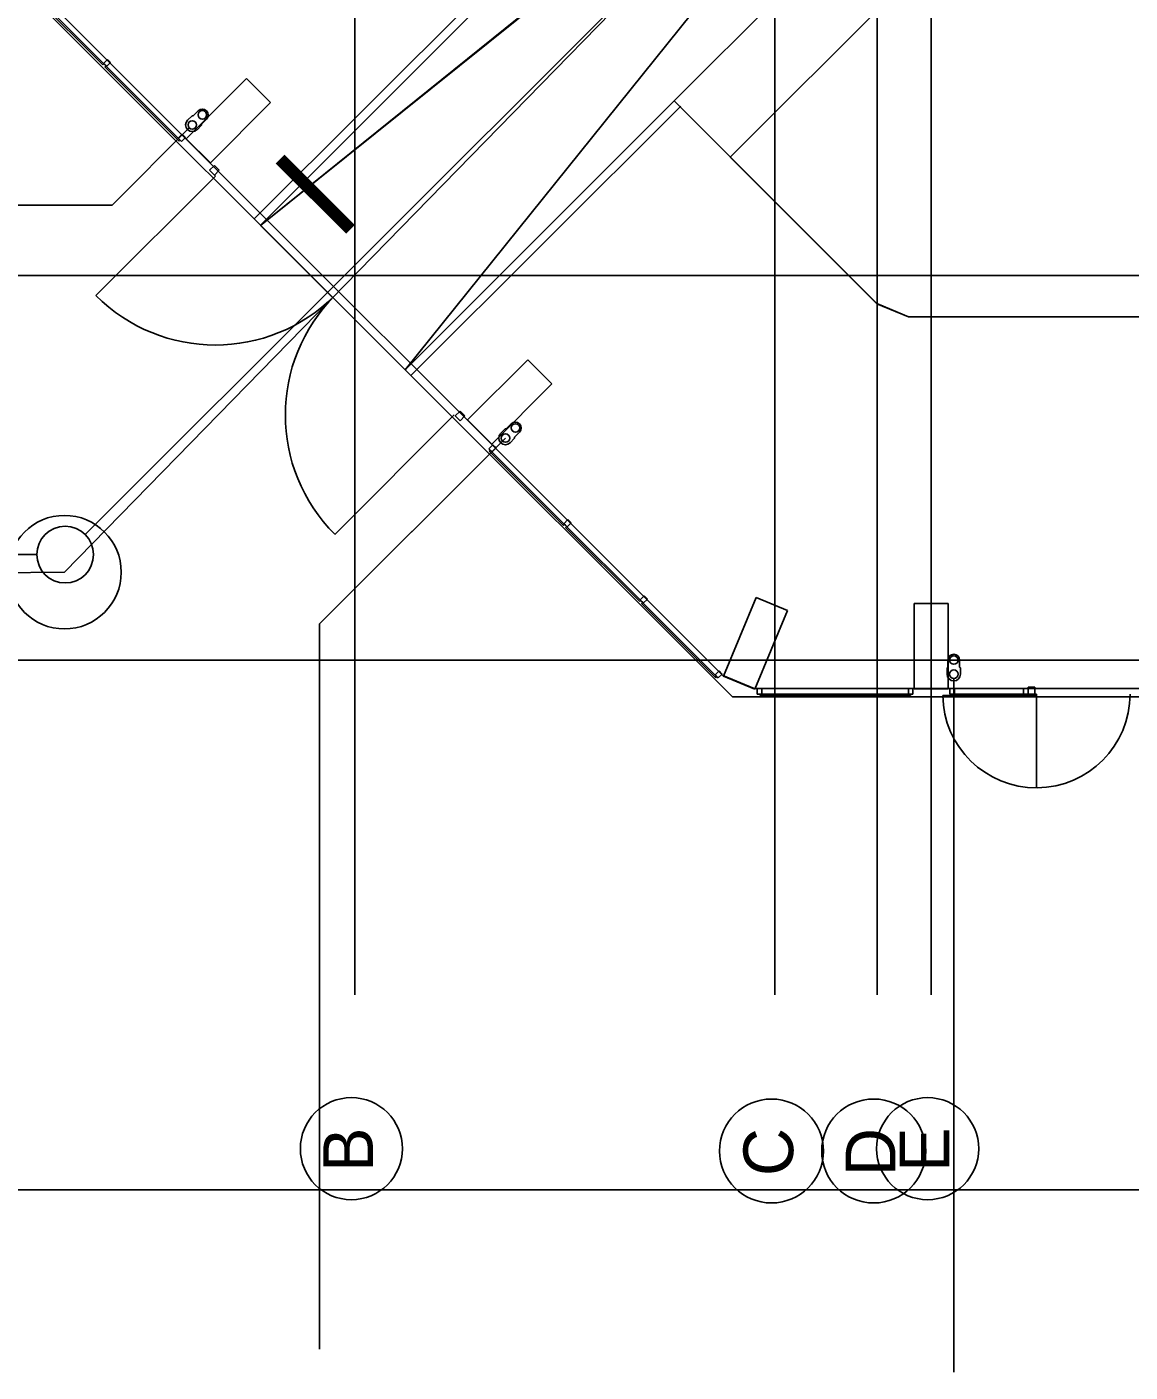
# Model space of a CAD drawing. Extents: x -264205 to -263659, y -1242401 to -1242060.
# Drawn here: x -263907.39 to -263887.96, y -1242253.35 to -1242229.65 of the extents above; entities that cross this region are included whole.
import ezdxf

# ---------------------------------------------------------------- set-up
doc = ezdxf.new("R2010")
doc.units = 0
for name, color, linetype in [('KFA_SO_40-2-II_DAZDOVA_KANALIZACIA', 7, 'Continuous'), ('OBRUBNIKY_KOMUNIKACIE_PROJEKT', 7, 'Continuous'), ('OSI_STAVBY_KFA', 7, 'Continuous'), ('SITUACIA_DSP_2D', 7, 'Continuous')]:
    doc.layers.add(name, color=color, linetype=linetype)

msp = doc.modelspace()

# ---------------------------------------------------------------- linework, layer by layer
at = {"layer": 'KFA_SO_40-2-II_DAZDOVA_KANALIZACIA'}
msp.add_line((-263926.723, -1242239.4), (-263906.731, -1242239.259), dxfattribs=at)
msp.add_lwpolyline([(-263814.907, -1242107.856), (-263815.198, -1242164.443), (-263815.189, -1242220.791), (-263852.152, -1242220.736), (-263888.701, -1242220.786), (-263906.731, -1242239.259)], dxfattribs=at)
msp.add_circle((-263906.731, -1242239.259), 1, dxfattribs=at)
at = {"layer": 'OBRUBNIKY_KOMUNIKACIE_PROJEKT'}
for p, q in [((-263890.254, -1242222.659), (-263903.277, -1242233.148)), ((-263900.731, -1242235.694), (-263890.254, -1242222.659)), ((-263895.995, -1242230.956), (-263890.391, -1242225.352)), ((-263894.968, -1242241.457), (-263909.043, -1242227.382)), ((-263898.65, -1242228.301), (-263903.39, -1242233.035)), ((-263898.544, -1242228.407), (-263903.281, -1242233.144)), ((-263900.731, -1242235.694), (-263895.982, -1242230.943)), ((-263892.424, -1242234.526), (-263895.994, -1242230.956)), ((-263900.629, -1242235.796), (-263895.875, -1242231.049)), ((-263903.39, -1242233.035), (-263900.629, -1242235.796)), ((-263903.281, -1242233.144), (-263900.731, -1242235.694)), ((-263903.277, -1242233.148), (-263900.731, -1242235.694)), ((-263891.868, -1242234.757), (-263892.424, -1242234.526)), ((-263822.79, -1242234.757), (-263891.868, -1242234.757)), ((-263822.79, -1242241.457), (-263894.968, -1242241.457))]:
    msp.add_line(p, q, dxfattribs=at)
at = {"layer": 'OSI_STAVBY_KFA'}
for p, q in [((-263901.618, -1242083.237), (-263901.618, -1242246.707)), ((-263894.218, -1242083.237), (-263894.218, -1242246.707)), ((-263892.418, -1242083.237), (-263892.418, -1242246.707)), ((-263891.468, -1242083.237), (-263891.468, -1242246.707)), ((-263792.653, -1242234.032), (-263911.523, -1242234.032)), ((-263792.653, -1242240.807), (-263911.523, -1242240.807))]:
    msp.add_line(p, q, dxfattribs=at)
for centre, radius in [((-263901.678, -1242249.416), 0.899), ((-263894.278, -1242249.457), 0.916), ((-263892.478, -1242249.457), 0.916), ((-263891.528, -1242249.416), 0.899)]:
    msp.add_circle(centre, radius, dxfattribs=at)
at = {"layer": 'SITUACIA_DSP_2D'}
for p, q in [((-263889.023, -1242221.253), (-263906.365, -1242238.596)), ((-263890.333, -1242222.748), (-263903.277, -1242233.148)), ((-263900.731, -1242235.694), (-263890.333, -1242222.748)), ((-263895.995, -1242230.956), (-263890.391, -1242225.352)), ((-263894.968, -1242241.457), (-263909.043, -1242227.382)), ((-263908.663, -1242227.55), (-263895.135, -1242241.078)), ((-263895.005, -1242231.945), (-263891.01, -1242227.95)), ((-263891.01, -1242227.95), (-263895.005, -1242231.945)), ((-263898.65, -1242228.301), (-263903.39, -1242233.035)), ((-263898.544, -1242228.407), (-263903.281, -1242233.144)), ((-263906.055, -1242230.32), (-263907.363, -1242229.012)), ((-263907.345, -1242228.994), (-263906.037, -1242230.303)), ((-263906.037, -1242230.303), (-263906.055, -1242230.32)), ((-263906.046, -1242230.294), (-263905.975, -1242230.223)), ((-263906.017, -1242230.322), (-263906.046, -1242230.294)), ((-263905.989, -1242230.351), (-263906.017, -1242230.322)), ((-263905.918, -1242230.28), (-263905.989, -1242230.351)), ((-263905.975, -1242230.223), (-263905.918, -1242230.28)), ((-263906.019, -1242230.356), (-263906.001, -1242230.338)), ((-263904.711, -1242231.664), (-263906.019, -1242230.356)), ((-263906.001, -1242230.338), (-263904.693, -1242231.647)), ((-263903.526, -1242230.561), (-263904.586, -1242231.622)), ((-263903.101, -1242230.985), (-263903.526, -1242230.561)), ((-263904.162, -1242232.046), (-263903.101, -1242230.985)), ((-263900.731, -1242235.694), (-263895.982, -1242230.943)), ((-263892.424, -1242234.526), (-263895.994, -1242230.956)), ((-263904.484, -1242231.218), (-263904.563, -1242231.296)), ((-263904.465, -1242231.218), (-263904.484, -1242231.218)), ((-263904.376, -1242231.13), (-263904.465, -1242231.218)), ((-263904.231, -1242231.275), (-263904.319, -1242231.364)), ((-263900.629, -1242235.796), (-263895.875, -1242231.049)), ((-263904.533, -1242231.432), (-263905.894, -1242232.793)), ((-263904.397, -1242231.462), (-263904.319, -1242231.383)), ((-263904.319, -1242231.383), (-263904.397, -1242231.462)), ((-263904.319, -1242231.364), (-263904.319, -1242231.383)), ((-263904.726, -1242231.613), (-263904.656, -1242231.543)), ((-263904.698, -1242231.642), (-263904.726, -1242231.613)), ((-263904.693, -1242231.647), (-263904.711, -1242231.664)), ((-263904.67, -1242231.67), (-263904.698, -1242231.642)), ((-263904.599, -1242231.599), (-263904.67, -1242231.67)), ((-263904.656, -1242231.543), (-263904.599, -1242231.599)), ((-263904.586, -1242231.622), (-263904.162, -1242232.046)), ((-263892.422, -1242234.528), (-263895.005, -1242231.945)), ((-263895.005, -1242231.945), (-263892.422, -1242234.528)), ((-263904.091, -1242232.093), (-263904.176, -1242232.178)), ((-263904.176, -1242232.178), (-263904.091, -1242232.263)), ((-263904.006, -1242232.178), (-263904.091, -1242232.093)), ((-263904.091, -1242232.263), (-263904.006, -1242232.178)), ((-263904.074, -1242232.281), (-263906.177, -1242234.384)), ((-263904.091, -1242232.263), (-263904.074, -1242232.281)), ((-263905.894, -1242232.793), (-263918.643, -1242232.793)), ((-263903.39, -1242233.035), (-263900.629, -1242235.796)), ((-263903.281, -1242233.144), (-263900.731, -1242235.694)), ((-263903.277, -1242233.148), (-263900.731, -1242235.694)), ((-263891.868, -1242234.757), (-263892.424, -1242234.526)), ((-263891.868, -1242234.757), (-263892.422, -1242234.528)), ((-263892.422, -1242234.528), (-263891.868, -1242234.757)), ((-263874.98, -1242234.757), (-263891.868, -1242234.757)), ((-263891.868, -1242234.757), (-263874.98, -1242234.757)), ((-263822.79, -1242234.757), (-263891.868, -1242234.757)), ((-263899.631, -1242236.576), (-263898.571, -1242235.516)), ((-263898.571, -1242235.516), (-263898.147, -1242235.94)), ((-263898.147, -1242235.94), (-263899.207, -1242237.001)), ((-263899.866, -1242236.488), (-263901.97, -1242238.592)), ((-263899.849, -1242236.506), (-263899.764, -1242236.421)), ((-263899.764, -1242236.421), (-263899.679, -1242236.506)), ((-263899.764, -1242236.591), (-263899.849, -1242236.506)), ((-263899.679, -1242236.506), (-263899.764, -1242236.591)), ((-263899.207, -1242237.001), (-263899.631, -1242236.576)), ((-263898.861, -1242236.645), (-263898.949, -1242236.733)), ((-263898.965, -1242236.895), (-263902.238, -1242240.168)), ((-263899.018, -1242236.948), (-263902.238, -1242240.168)), ((-263898.969, -1242236.733), (-263899.047, -1242236.812)), ((-263898.949, -1242236.733), (-263898.969, -1242236.733)), ((-263898.804, -1242236.899), (-263898.882, -1242236.977)), ((-263898.882, -1242236.977), (-263898.804, -1242236.899)), ((-263898.715, -1242236.791), (-263898.804, -1242236.879)), ((-263898.804, -1242236.879), (-263898.804, -1242236.899)), ((-263899.185, -1242237.014), (-263899.255, -1242237.084)), ((-263899.255, -1242237.084), (-263899.227, -1242237.113)), ((-263899.232, -1242237.108), (-263899.25, -1242237.125)), ((-263899.25, -1242237.125), (-263897.942, -1242238.434)), ((-263897.924, -1242238.416), (-263899.232, -1242237.108)), ((-263899.227, -1242237.113), (-263899.199, -1242237.141)), ((-263899.199, -1242237.141), (-263899.128, -1242237.07)), ((-263899.128, -1242237.07), (-263899.185, -1242237.014)), ((-263897.865, -1242238.333), (-263897.936, -1242238.404)), ((-263897.809, -1242238.389), (-263897.865, -1242238.333)), ((-263897.942, -1242238.434), (-263897.924, -1242238.416)), ((-263897.936, -1242238.404), (-263897.908, -1242238.432)), ((-263897.908, -1242238.432), (-263897.88, -1242238.46)), ((-263897.888, -1242238.452), (-263897.906, -1242238.469)), ((-263897.906, -1242238.469), (-263896.598, -1242239.778)), ((-263896.58, -1242239.76), (-263897.888, -1242238.452)), ((-263897.88, -1242238.46), (-263897.809, -1242238.389)), ((-263907.219, -1242238.949), (-263926.43, -1242238.949)), ((-263896.598, -1242239.778), (-263896.58, -1242239.76)), ((-263896.522, -1242239.677), (-263896.592, -1242239.748)), ((-263896.592, -1242239.748), (-263896.564, -1242239.776)), ((-263896.566, -1242239.809), (-263896.548, -1242239.792)), ((-263895.258, -1242241.118), (-263896.566, -1242239.809)), ((-263896.564, -1242239.776), (-263896.536, -1242239.804)), ((-263896.548, -1242239.792), (-263895.24, -1242241.1)), ((-263896.536, -1242239.804), (-263896.465, -1242239.733)), ((-263896.465, -1242239.733), (-263896.522, -1242239.677)), ((-263894.551, -1242239.702), (-263895.125, -1242241.088)), ((-263893.997, -1242239.932), (-263894.551, -1242239.702)), ((-263894.571, -1242241.318), (-263893.997, -1242239.932)), ((-263891.768, -1242241.312), (-263891.768, -1242239.812)), ((-263891.768, -1242239.812), (-263891.168, -1242239.812)), ((-263891.168, -1242239.812), (-263891.168, -1242241.312)), ((-263902.238, -1242240.168), (-263902.238, -1242252.949)), ((-263891.171, -1242240.932), (-263891.185, -1242240.946)), ((-263891.185, -1242240.946), (-263891.185, -1242241.057)), ((-263891.171, -1242240.807), (-263891.171, -1242240.932)), ((-263890.965, -1242240.807), (-263890.965, -1242240.932)), ((-263890.965, -1242240.932), (-263890.951, -1242240.946)), ((-263890.951, -1242241.057), (-263890.951, -1242240.946)), ((-263890.951, -1242240.946), (-263890.951, -1242241.057)), ((-263895.202, -1242240.996), (-263895.273, -1242241.067)), ((-263895.273, -1242241.067), (-263895.245, -1242241.095)), ((-263895.24, -1242241.1), (-263895.258, -1242241.118)), ((-263895.245, -1242241.095), (-263895.216, -1242241.123)), ((-263895.216, -1242241.123), (-263895.146, -1242241.053)), ((-263895.146, -1242241.053), (-263895.202, -1242240.996)), ((-263895.135, -1242241.078), (-263894.581, -1242241.307)), ((-263895.125, -1242241.088), (-263894.571, -1242241.318)), ((-263891.068, -1242241.132), (-263891.068, -1242253.353)), ((-263822.79, -1242241.457), (-263894.968, -1242241.457)), ((-263894.581, -1242241.307), (-263822.79, -1242241.307)), ((-263894.531, -1242241.407), (-263894.531, -1242241.307)), ((-263894.531, -1242241.307), (-263894.451, -1242241.307)), ((-263894.491, -1242241.407), (-263894.531, -1242241.407)), ((-263894.451, -1242241.407), (-263894.491, -1242241.407)), ((-263891.828, -1242241.407), (-263894.478, -1242241.407)), ((-263894.478, -1242241.407), (-263894.478, -1242241.432)), ((-263894.478, -1242241.432), (-263891.828, -1242241.432)), ((-263894.451, -1242241.307), (-263894.451, -1242241.407)), ((-263891.868, -1242241.407), (-263891.868, -1242241.307)), ((-263891.868, -1242241.307), (-263891.788, -1242241.307)), ((-263891.828, -1242241.407), (-263891.868, -1242241.407)), ((-263891.828, -1242241.432), (-263891.828, -1242241.407)), ((-263891.788, -1242241.407), (-263891.828, -1242241.407)), ((-263891.788, -1242241.307), (-263891.788, -1242241.407)), ((-263891.168, -1242241.312), (-263891.768, -1242241.312)), ((-263891.263, -1242241.432), (-263889.613, -1242241.432)), ((-263891.058, -1242241.307), (-263891.138, -1242241.307)), ((-263891.138, -1242241.307), (-263891.138, -1242241.407)), ((-263891.138, -1242241.407), (-263891.098, -1242241.407)), ((-263891.098, -1242241.432), (-263891.098, -1242241.407)), ((-263891.098, -1242241.407), (-263889.798, -1242241.407)), ((-263891.098, -1242241.407), (-263891.058, -1242241.407)), ((-263889.798, -1242241.432), (-263891.098, -1242241.432)), ((-263891.058, -1242241.407), (-263891.058, -1242241.307)), ((-263889.838, -1242241.407), (-263889.838, -1242241.307)), ((-263889.838, -1242241.307), (-263889.758, -1242241.307)), ((-263889.798, -1242241.407), (-263889.838, -1242241.407)), ((-263889.798, -1242241.407), (-263889.798, -1242241.432)), ((-263889.758, -1242241.407), (-263889.798, -1242241.407)), ((-263889.638, -1242241.287), (-263889.758, -1242241.287)), ((-263889.758, -1242241.287), (-263889.758, -1242241.407)), ((-263889.758, -1242241.307), (-263889.758, -1242241.407)), ((-263889.758, -1242241.407), (-263889.638, -1242241.407)), ((-263889.638, -1242241.407), (-263889.638, -1242241.287)), ((-263889.638, -1242241.407), (-263889.613, -1242241.407)), ((-263889.613, -1242241.407), (-263889.613, -1242243.057)), ((-263924.143, -1242250.14), (-263822.79, -1242250.14))]:
    msp.add_line(p, q, dxfattribs=at)
for centre, radius in [((-263904.303, -1242231.202), 0.075), ((-263904.48, -1242231.379), 0.075), ((-263898.788, -1242236.718), 0.075), ((-263898.965, -1242236.895), 0.075), ((-263906.719, -1242238.949), 0.5), ((-263891.068, -1242240.807), 0.075), ((-263891.068, -1242241.057), 0.075)]:
    msp.add_circle(centre, radius, dxfattribs=at)
for centre, radius, start, end in [((-263904.303, -1242231.202), 0.103, 315, 135), ((-263904.48, -1242231.379), 0.117, 135, 315), ((-263904.074, -1242232.281), 2.975, 225.0001, 315.0001), ((-263899.866, -1242236.488), 2.975, 134.9999, 224.9999), ((-263898.788, -1242236.718), 0.103, 315, 135), ((-263898.965, -1242236.895), 0.117, 135, 315), ((-263891.068, -1242240.807), 0.103, 360, 180), ((-263891.068, -1242241.057), 0.117, 180, 360), ((-263889.613, -1242241.407), 1.65, 180.8682, 0)]:
    msp.add_arc(centre, radius, start, end, dxfattribs=at)

# ---------------------------------------------------------------- texts
at = {"layer": 'OSI_STAVBY_KFA'}
for s, p in [('B', (-263901.297, -1242249.824)), ('C', (-263893.897, -1242249.898)), ('D', (-263892.097, -1242249.898)), ('E', (-263891.147, -1242249.824))]:
    msp.add_text(s, height=0.875, rotation=90, dxfattribs=at).set_placement(p)
at = {"layer": 'SITUACIA_DSP_2D'}
msp.add_text('I', height=1.75, rotation=45.0119, dxfattribs=at).set_placement((-263901.924, -1242233.448))

doc.saveas('drawing.dxf')
